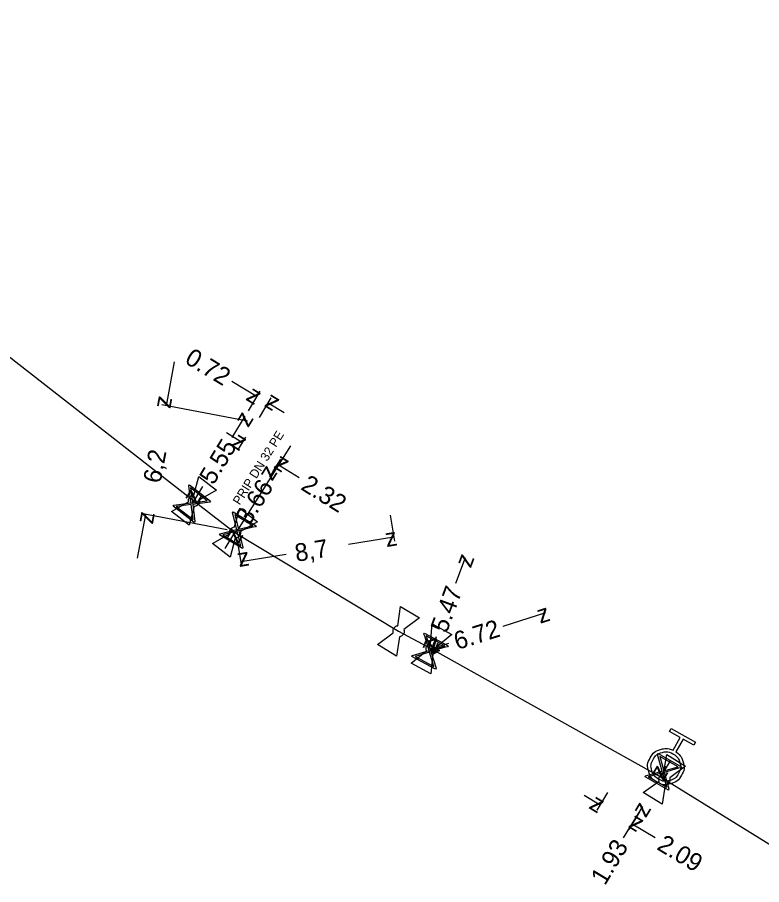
# Model space of a CAD drawing. Extents: x -638315 to -636370, y -1116147 to -1115110.
# Drawn here: x -637210.5 to -637168.75, y -1115973.26 to -1115924.63 of the extents above; entities that cross this region are included whole.
import ezdxf

# ---------------------------------------------------------------- set-up
doc = ezdxf.new("R2010")
doc.units = 0
for name, color, linetype in [('Default', 7, 'Continuous'), ('VP Hydrant', 7, 'Continuous'), ('VP Kótování', 7, 'Continuous'), ('VP Lomový bod', 7, 'Continuous'), ('VP Popis přípojky', 7, 'Continuous'), ('VP Přípojka', 7, 'Continuous'), ('VP Řad', 7, 'Continuous'), ('VP Šoupě', 7, 'Continuous')]:
    doc.layers.add(name, color=color, linetype=linetype)

msp = doc.modelspace()

# ---------------------------------------------------------------- linework, layer by layer
at = {"layer": 'Default'}
for points in [[(-637200.894, -1115951.803), (-637200.905, -1115951.751), (-637200.897, -1115951.697), (-637200.885, -1115951.614), (-637200.834, -1115951.55), (-637200.784, -1115951.485), (-637200.704, -1115951.452), (-637200.655, -1115951.431), (-637200.602, -1115951.429)], [(-637200.28, -1115951.68), (-637200.27, -1115951.731), (-637200.277, -1115951.784), (-637200.291, -1115951.869), (-637200.341, -1115951.934), (-637200.391, -1115951.998), (-637200.469, -1115952.03), (-637200.52, -1115952.051), (-637200.572, -1115952.054)], [(-637198.597, -1115953.583), (-637198.608, -1115953.531), (-637198.6, -1115953.477), (-637198.588, -1115953.394), (-637198.538, -1115953.329), (-637198.488, -1115953.264), (-637198.407, -1115953.231), (-637198.359, -1115953.21), (-637198.306, -1115953.207)], [(-637197.983, -1115953.458), (-637197.973, -1115953.508), (-637197.98, -1115953.562), (-637197.993, -1115953.647), (-637198.043, -1115953.712), (-637198.093, -1115953.776), (-637198.171, -1115953.809), (-637198.221, -1115953.83), (-637198.274, -1115953.832)], [(-637189.407, -1115959.148), (-637189.424, -1115959.098), (-637189.422, -1115959.043), (-637189.42, -1115958.959), (-637189.378, -1115958.889), (-637189.336, -1115958.819), (-637189.26, -1115958.776), (-637189.214, -1115958.75), (-637189.162, -1115958.741)], [(-637188.812, -1115958.952), (-637188.796, -1115959.002), (-637188.797, -1115959.055), (-637188.8, -1115959.141), (-637188.843, -1115959.212), (-637188.885, -1115959.282), (-637188.958, -1115959.323), (-637189.006, -1115959.35), (-637189.058, -1115959.358)], [(-637187.552, -1115960.152), (-637187.571, -1115960.103), (-637187.572, -1115960.048), (-637187.574, -1115959.964), (-637187.536, -1115959.892), (-637187.497, -1115959.82), (-637187.424, -1115959.774), (-637187.379, -1115959.745), (-637187.328, -1115959.734)], [(-637186.967, -1115959.927), (-637186.949, -1115959.975), (-637186.947, -1115960.029), (-637186.946, -1115960.115), (-637186.985, -1115960.187), (-637187.023, -1115960.259), (-637187.094, -1115960.304), (-637187.14, -1115960.334), (-637187.192, -1115960.345)], [(-637173.554, -1115965.815), (-637173.254, -1115966.016), (-637173.156, -1115966.369), (-637173.045, -1115966.767), (-637173.249, -1115967.13), (-637173.451, -1115967.491), (-637173.849, -1115967.603), (-637174.247, -1115967.715), (-637174.61, -1115967.511), (-637174.97, -1115967.31), (-637175.083, -1115966.912), (-637175.196, -1115966.514), (-637174.994, -1115966.153), (-637174.791, -1115965.79), (-637174.394, -1115965.676), (-637174.041, -1115965.574), (-637173.714, -1115965.726)], [(-637173.724, -1115965.928), (-637174.019, -1115965.763), (-637174.342, -1115965.854), (-637174.665, -1115965.945), (-637174.83, -1115966.24), (-637174.995, -1115966.535), (-637174.904, -1115966.858), (-637174.813, -1115967.181), (-637174.518, -1115967.346), (-637174.225, -1115967.51), (-637173.901, -1115967.419), (-637173.577, -1115967.329), (-637173.412, -1115967.034), (-637173.247, -1115966.739), (-637173.338, -1115966.416), (-637173.429, -1115966.093), (-637173.724, -1115965.928)], [(-637174.498, -1115967.455), (-637174.515, -1115967.404), (-637174.512, -1115967.35), (-637174.509, -1115967.266), (-637174.466, -1115967.196), (-637174.423, -1115967.126), (-637174.347, -1115967.085), (-637174.301, -1115967.059), (-637174.249, -1115967.051)], [(-637173.901, -1115967.266), (-637173.886, -1115967.315), (-637173.887, -1115967.369), (-637173.892, -1115967.455), (-637173.935, -1115967.525), (-637173.978, -1115967.594), (-637174.051, -1115967.635), (-637174.099, -1115967.661), (-637174.152, -1115967.669)]]:
    msp.add_open_spline(points, degree=3, dxfattribs=at)
at = {"layer": 'VP Hydrant'}
msp.add_lwpolyline([(-637173.714, -1115965.726), (-637173.313, -1115965.01), (-637173.915, -1115964.673), (-637173.826, -1115964.513), (-637172.462, -1115965.276), (-637172.552, -1115965.436), (-637173.153, -1115965.099), (-637173.554, -1115965.815)], dxfattribs=at)
at = {"layer": 'VP Kótování'}
for points in [[(-637201.69, -1115943.955), (-637202.152, -1115946.412)], [(-637198.462, -1115945.029), (-637197.05, -1115945.883)], [(-637197.536, -1115946.687), (-637196.869, -1115945.584)], [(-637196.919, -1115947.06), (-637196.252, -1115945.957)], [(-637197.591, -1115947.268), (-637202.397, -1115946.366)], [(-637195.534, -1115946.799), (-637196.433, -1115946.256)], [(-637198.445, -1115948.193), (-637197.717, -1115946.987)], [(-637198.763, -1115947.916), (-637197.872, -1115948.472)], [(-637198.135, -1115948.893), (-637197.687, -1115948.175)], [(-637196.169, -1115950.12), (-637195.721, -1115949.402)], [(-637195.798, -1115949.526), (-637196.354, -1115950.417)], [(-637194.687, -1115950.46), (-637195.906, -1115949.699)], [(-637200.105, -1115950.941), (-637200.588, -1115951.742)], [(-637203.756, -1115954.963), (-637203.295, -1115952.505)], [(-637198.735, -1115953.361), (-637203.541, -1115952.459)], [(-637189.577, -1115952.541), (-637189.337, -1115954.009)], [(-637198.846, -1115954.411), (-637198.29, -1115953.52)], [(-637191.925, -1115954.179), (-637189.377, -1115953.762)], [(-637198.163, -1115953.947), (-637197.923, -1115955.415)], [(-637195.415, -1115954.751), (-637197.963, -1115955.168)], [(-637185.893, -1115956.349), (-637185.36, -1115954.91)], [(-637183.248, -1115958.769), (-637180.85, -1115958.01)], [(-637187.007, -1115959.358), (-637187.26, -1115960.04)], [(-637186.306, -1115959.738), (-637187.26, -1115960.04)], [(-637173.882, -1115966.323), (-637174.424, -1115967.222)], [(-637178.707, -1115968.239), (-637177.808, -1115968.781)], [(-637177.391, -1115968.09), (-637177.989, -1115969.081)], [(-637176.489, -1115970.644), (-637175.419, -1115968.871)], [(-637175.6, -1115969.171), (-637176.198, -1115970.162)], [(-637174.725, -1115970.643), (-637176.017, -1115969.862)]]:
    msp.add_lwpolyline(points, dxfattribs=at)
at = {"layer": 'VP Lomový bod'}
for points in [[(-637200.602, -1115951.429), (-637200.313, -1115950.371)], [(-637200.313, -1115950.371), (-637199.327, -1115951.139), (-637200.28, -1115951.68)], [(-637200.572, -1115952.054), (-637200.863, -1115953.112), (-637201.849, -1115952.344), (-637200.894, -1115951.803)], [(-637198.306, -1115953.207), (-637198.02, -1115952.149)], [(-637198.02, -1115952.149), (-637197.031, -1115952.914), (-637197.983, -1115953.458)], [(-637198.274, -1115953.832), (-637198.561, -1115954.891), (-637199.55, -1115954.126), (-637198.597, -1115953.583)], [(-637189.162, -1115958.741), (-637189.001, -1115957.657)], [(-637189.001, -1115957.657), (-637187.93, -1115958.302), (-637188.812, -1115958.952)], [(-637187.328, -1115959.734), (-637187.221, -1115958.643)], [(-637187.221, -1115958.643), (-637186.119, -1115959.232), (-637186.967, -1115959.927)], [(-637189.058, -1115959.358), (-637189.22, -1115960.444), (-637190.291, -1115959.799), (-637189.407, -1115959.148)], [(-637187.192, -1115960.345), (-637187.299, -1115961.437), (-637188.401, -1115960.847), (-637187.552, -1115960.152)], [(-637174.249, -1115967.051), (-637174.074, -1115965.969)], [(-637174.074, -1115965.969), (-637173.011, -1115966.626), (-637173.901, -1115967.266)], [(-637174.152, -1115967.669), (-637174.326, -1115968.752), (-637175.389, -1115968.095), (-637174.498, -1115967.455)]]:
    msp.add_lwpolyline(points, dxfattribs=at)
at = {"layer": 'VP Přípojka'}
for points in [[(-637198.29, -1115953.52), (-637198.13, -1115953.39), (-637195.155, -1115948.655)], [(-637200.71, -1115951.9), (-637200.588, -1115951.742)], [(-637187.374, -1115960.204), (-637187.26, -1115960.04)], [(-637174.12, -1115966.64), (-637174.254, -1115966.908), (-637174.424, -1115967.222)]]:
    msp.add_lwpolyline(points, dxfattribs=at)
at = {"layer": 'VP Řad'}
msp.add_lwpolyline([(-637237.94, -1115924.63), (-637212.993, -1115942.084), (-637200.588, -1115951.742), (-637198.29, -1115953.52), (-637189.11, -1115959.05), (-637187.26, -1115960.04), (-637174.427, -1115967.22), (-637166.44, -1115972.16)], dxfattribs=at)
at = {"layer": 'VP Šoupě'}
for points in [[(-637200.844, -1115950.848), (-637199.658, -1115951.766), (-637199.698, -1115951.818), (-637199.826, -1115951.83), (-637200.66, -1115951.937), (-637200.536, -1115952.9), (-637200.576, -1115952.952), (-637201.762, -1115952.034), (-637201.722, -1115951.982), (-637200.758, -1115951.861), (-637200.865, -1115951.028), (-637200.885, -1115950.9), (-637200.844, -1115950.848)], [(-637200.777, -1115951.018), (-637200.671, -1115951.85), (-637199.841, -1115951.743), (-637200.777, -1115951.018)], [(-637200.639, -1115952.785), (-637200.747, -1115951.948), (-637201.581, -1115952.056), (-637200.639, -1115952.785)], [(-637198.386, -1115952.36), (-637197.101, -1115953.134), (-637197.135, -1115953.191), (-637197.261, -1115953.217), (-637198.076, -1115953.421), (-637197.841, -1115954.363), (-637197.875, -1115954.419), (-637199.16, -1115953.645), (-637199.126, -1115953.589), (-637198.182, -1115953.357), (-637198.386, -1115952.541), (-637198.42, -1115952.417), (-637198.386, -1115952.36)], [(-637198.299, -1115952.522), (-637198.097, -1115953.335), (-637197.285, -1115953.133), (-637198.299, -1115952.522)], [(-637197.957, -1115954.26), (-637198.161, -1115953.442), (-637198.977, -1115953.646), (-637197.957, -1115954.26)], [(-637187.658, -1115959.155), (-637186.335, -1115959.862), (-637186.366, -1115959.921), (-637186.49, -1115959.954), (-637187.294, -1115960.198), (-637187.012, -1115961.127), (-637187.043, -1115961.185), (-637188.366, -1115960.477), (-637188.334, -1115960.419), (-637187.404, -1115960.14), (-637187.648, -1115959.336), (-637187.689, -1115959.213), (-637187.658, -1115959.155)], [(-637187.563, -1115959.312), (-637187.32, -1115960.114), (-637186.519, -1115959.87), (-637187.563, -1115959.312)], [(-637187.133, -1115961.03), (-637187.378, -1115960.224), (-637188.183, -1115960.469), (-637187.133, -1115961.03)], [(-637174.555, -1115965.915), (-637173.246, -1115966.647), (-637173.278, -1115966.704), (-637173.403, -1115966.735), (-637174.211, -1115966.965), (-637173.946, -1115967.898), (-637173.978, -1115967.956), (-637175.287, -1115967.224), (-637175.255, -1115967.166), (-637174.319, -1115966.904), (-637174.549, -1115966.096), (-637174.587, -1115965.972), (-637174.555, -1115965.915)], [(-637174.463, -1115966.073), (-637174.235, -1115966.88), (-637173.429, -1115966.652), (-637174.463, -1115966.073)], [(-637174.065, -1115967.8), (-637174.295, -1115966.989), (-637175.104, -1115967.218), (-637174.065, -1115967.8)]]:
    msp.add_lwpolyline(points, dxfattribs=at)

# ---------------------------------------------------------------- texts
at = {"layer": 'VP Kótování'}
for s, rotation, p in [('0.72', 328.8455, (-637201.166, -1115943.979)), ('z', 328.8454, (-637197.736, -1115946.052)), ('z', 259.3699, (-637202.551, -1115945.828)), ('z', 148.8454, (-637195.746, -1115946.087)), ('z', 58.877, (-637197.547, -1115947.673)), ('z', 328.0313, (-637198.561, -1115948.632)), ('5.55', 58.877, (-637199.496, -1115950.9)), ('6,2', 79.3699, (-637202.466, -1115950.797)), ('z', 148.0313, (-637195.217, -1115949.54)), ('z', 238.0395, (-637196.514, -1115949.728)), ('2.32', 328.0313, (-637194.655, -1115951.069)), ('3.66', 58.0395, (-637197.473, -1115953.155)), ('z', 238.877, (-637200.758, -1115951.056)), ('z', 79.3699, (-637202.896, -1115953.089)), ('z', 58.0395, (-637198.13, -1115954.209)), ('8,7', 9.2976, (-637194.841, -1115955.164)), ('z', 9.2976, (-637189.79, -1115954.337)), ('z', 189.2976, (-637197.55, -1115954.594)), ('z', 69.6769, (-637185.065, -1115955.553)), ('5.47', 69.6769, (-637186.417, -1115959.204)), ('z', 17.5726, (-637181.176, -1115958.638)), ('6.72', 17.5726, (-637185.822, -1115960.109)), ('z', 249.6769, (-637187.555, -1115959.397)), ('z', 197.5726, (-637186.934, -1115959.412)), ('z', 238.8934, (-637174.594, -1115966.536)), ('z', 328.8859, (-637178.495, -1115968.951)), ('z', 58.8934, (-637175.249, -1115969.557)), ('z', 148.8859, (-637175.331, -1115969.693)), ('1.93', 58.8934, (-637177.537, -1115973.35)), ('2.09', 328.8859, (-637174.683, -1115971.252))]:
    msp.add_text(s, height=1, rotation=rotation, dxfattribs=at).set_placement(p)
at = {"layer": 'VP Popis přípojky'}
msp.add_text('PRIP DN 32 PE', height=0.5, rotation=57.8553, dxfattribs=at).set_placement((-637198.023, -1115952.012))

doc.saveas('drawing.dxf')
